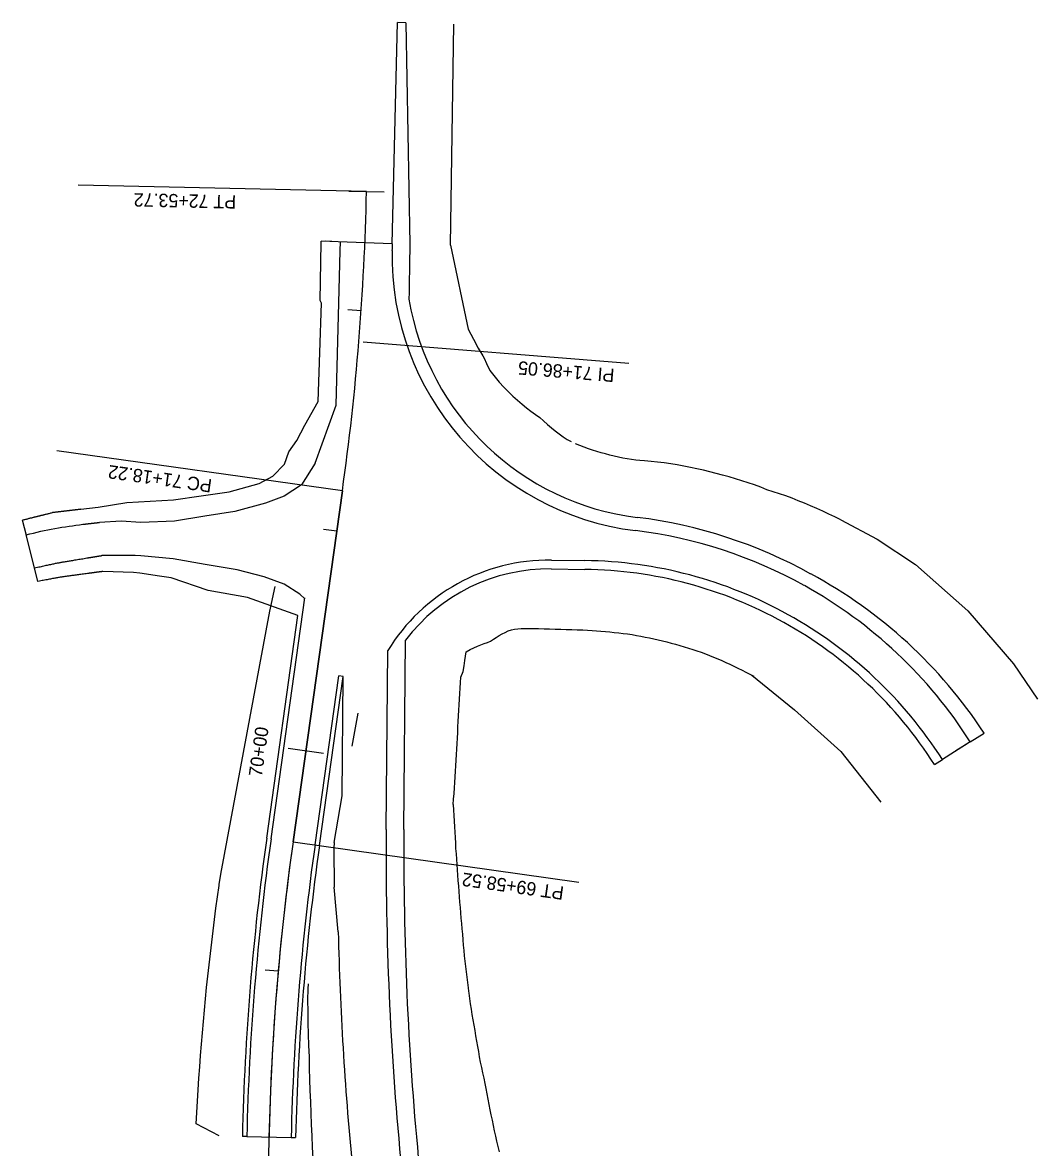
# Model space of a CAD drawing. Extents: x 1304554 to 1314558, y 2088110 to 2090513.
# Drawn here: x 1313853 to 1314311, y 2089937 to 2090444 of the extents above; entities that cross this region are included whole.
import ezdxf

# ---------------------------------------------------------------- set-up
doc = ezdxf.new("R2010")
doc.units = 0
for name, color, linetype in [('MOT_Striping_Stage 2B', 7, 'Continuous'), ('R_Horz Alg', 7, 'Continuous'), ('R_Horz Alg Annot', 7, 'Continuous'), ('R_Horz Alg Stationing', 7, 'Continuous'), ('R_Horz Alg Stationing_Side Road', 7, 'Continuous'), ('R_Proposed Const Limits', 7, 'Continuous'), ('R_Proposed Road', 7, 'Continuous'), ('R_Shoulder', 7, 'Continuous'), ('S_EDGE_PAVEMENT', 7, 'Continuous'), ('S_Striping', 7, 'Continuous')]:
    doc.layers.add(name, color=color, linetype=linetype)

msp = doc.modelspace()

# ---------------------------------------------------------------- linework, layer by layer
at = {"layer": 'MOT_Striping_Stage 2B'}
msp.add_lwpolyline([(1313980.63, 2090184.34), (1313978.35, 2090186.41), (1313971.27, 2090190.88), (1313962.27, 2090194.23), (1313950.11, 2090197.37), (1313935.68, 2090199.83), (1313921.26, 2090202.29), (1313906.77, 2090203.63), (1313904.2, 2090203.8), (1313889.17, 2090203.82)], dxfattribs=at)
for points in [[(1313858.82, 2090198.24), (1313866.61, 2090200.04), (1313874.52, 2090201.43), (1313882.45, 2090202.73)], [(1313882.45, 2090202.73), (1313884.69, 2090203.1), (1313886.93, 2090203.46), (1313889.17, 2090203.82)]]:
    msp.add_open_spline(points, degree=2, dxfattribs=at)
at = {"layer": 'R_Horz Alg'}
for p, q in [((1313997.56, 2090232.93), (1313975.33, 2090074.78)), ((1313975.33, 2090074.78), (1313997.56, 2090232.93))]:
    msp.add_line(p, q, dxfattribs=at)
for centre, start, end in [((1312862.79, 2090392.41), 352, 358.77499), ((1312862.79, 2090392.41), 352, 358.77499), ((1315110.09, 2089915.3), 172, 187), ((1315110.09, 2089915.3), 172, 178.67589)]:
    msp.add_arc(centre, 1145.92, start, end, dxfattribs=at)
at = {"layer": 'R_Horz Alg Annot'}
for points in [[(1314008.45, 2090367.91), (1313878.48, 2090370.69)], [(1314007, 2090300.1), (1314126.61, 2090290.45)], [(1313997.56, 2090232.93), (1313868.82, 2090251.02)], [(1313975.33, 2090074.78), (1314104.07, 2090056.69)]]:
    msp.add_lwpolyline(points, dxfattribs=at)
at = {"layer": 'R_Horz Alg Stationing'}
for points in [[(1314000.45, 2090368.08), (1314016.45, 2090367.74)], [(1314000.45, 2090368.08), (1314016.45, 2090367.74)], [(1314000.05, 2090314.66), (1314006.04, 2090314.25)], [(1313989.08, 2090215.72), (1313995.02, 2090214.89)], [(1313973.18, 2090116.97), (1313989.03, 2090114.75)], [(1313962.69, 2090017.18), (1313968.67, 2090016.65)]]:
    msp.add_lwpolyline(points, dxfattribs=at)
at = {"layer": 'R_Horz Alg Stationing_Side Road'}
msp.add_lwpolyline([(1314279.15, 2090118.99), (1314274.09, 2090115.77)], dxfattribs=at)
at = {"layer": 'R_Proposed Const Limits'}
for p, q in [((1314046.26, 2090343.75), (1314047.79, 2090443.25)), ((1313942.75, 2090060.17), (1313964.93, 2090178.72))]:
    msp.add_line(p, q, dxfattribs=at)
for points in [[(1314046.26, 2090343.75), (1314054.24, 2090305.79), (1314056.64, 2090301.31), (1314058.76, 2090297.34), (1314060.81, 2090293.79), (1314061.43, 2090292.78), (1314062.5, 2090290.38), (1314064.09, 2090287.15)], [(1314064.09, 2090287.15), (1314068.17, 2090281.94), (1314070.3, 2090279.69), (1314072.39, 2090277.59), (1314074.46, 2090275.63), (1314076.51, 2090273.78), (1314078.53, 2090272.04), (1314080.54, 2090270.39), (1314082.53, 2090268.84), (1314084.54, 2090267.42), (1314086.54, 2090266.08), (1314088.28, 2090264.49), (1314090, 2090262.93), (1314091.74, 2090261.44), (1314093.48, 2090260.01), (1314095.24, 2090258.64), (1314097.03, 2090257.37), (1314098.84, 2090256.16), (1314100.75, 2090255.18)], [(1314222.24, 2090219.87), (1314219.53, 2090221.2), (1314216.81, 2090222.5), (1314214.08, 2090223.76), (1314211.33, 2090224.99), (1314208.57, 2090226.19), (1314205.8, 2090227.36), (1314203.01, 2090228.49), (1314200.22, 2090229.61), (1314197.41, 2090230.67), (1314194.59, 2090231.69), (1314191.71, 2090232.57), (1314188.84, 2090233.45), (1314186.1, 2090234.65), (1314183.27, 2090235.64), (1314180.43, 2090236.58), (1314177.57, 2090237.49), (1314174.72, 2090238.4), (1314171.84, 2090239.24), (1314168.95, 2090240.03), (1314166.06, 2090240.79), (1314163.16, 2090241.54), (1314160.25, 2090242.26), (1314157.33, 2090242.9), (1314154.39, 2090243.5), (1314151.46, 2090244.08), (1314148.52, 2090244.67), (1314145.57, 2090245.15), (1314142.61, 2090245.58), (1314139.64, 2090245.96), (1314136.66, 2090246.22), (1314133.68, 2090246.48), (1314131.7, 2090246.62), (1314129.76, 2090246.81), (1314127.82, 2090247.05), (1314125.88, 2090247.35), (1314123.94, 2090247.7), (1314121.99, 2090248.1), (1314120.03, 2090248.56), (1314118.06, 2090249.07), (1314116.08, 2090249.6), (1314114.17, 2090250.11), (1314112.26, 2090250.67), (1314110.34, 2090251.28), (1314108.42, 2090251.94), (1314106.49, 2090252.64), (1314104.56, 2090253.4), (1314102.63, 2090254.21)], [(1314222.24, 2090219.87), (1314238.55, 2090211.26), (1314255.87, 2090199.73), (1314279.52, 2090178.98), (1314299.98, 2090154.96), (1314310.86, 2090139.11)], [(1313964.93, 2090178.72), (1313965.95, 2090183.63), (1313966.95, 2090188.54), (1313967.21, 2090189.8)], [(1313964.93, 2090178.72), (1313965.95, 2090183.63), (1313966.95, 2090188.54), (1313967.21, 2090189.8)], [(1314053.37, 2090160.46), (1314055.23, 2090161.43), (1314056.83, 2090162.21), (1314058.4, 2090162.92), (1314059.94, 2090163.57), (1314061.45, 2090164.15), (1314062.94, 2090164.67), (1314064.35, 2090165.28), (1314065.63, 2090166.14), (1314066.93, 2090166.96), (1314068.26, 2090167.74), (1314069.6, 2090168.47), (1314070.96, 2090169.17), (1314072.34, 2090169.83), (1314073.75, 2090170.4), (1314075.21, 2090170.68), (1314076.69, 2090170.85), (1314078.16, 2090170.92), (1314079.63, 2090170.95), (1314081.1, 2090170.93), (1314083.45, 2090170.91), (1314085.95, 2090170.88), (1314088.45, 2090170.84), (1314090.95, 2090170.76), (1314093.45, 2090170.69), (1314095.95, 2090170.62), (1314098.45, 2090170.55), (1314100.95, 2090170.48), (1314103.45, 2090170.39), (1314105.94, 2090170.28), (1314108.06, 2090170.18), (1314110.07, 2090170.05), (1314112.08, 2090169.91), (1314114.09, 2090169.75), (1314116.1, 2090169.59), (1314118.11, 2090169.41), (1314120.11, 2090169.2), (1314122.11, 2090168.98), (1314124.11, 2090168.74), (1314126.11, 2090168.48), (1314128.1, 2090168.19), (1314130.08, 2090167.85), (1314132.06, 2090167.48), (1314134.04, 2090167.09), (1314136.01, 2090166.69), (1314137.98, 2090166.27), (1314139.94, 2090165.82), (1314141.89, 2090165.36), (1314143.85, 2090164.88), (1314145.79, 2090164.38), (1314147.74, 2090163.85), (1314149.67, 2090163.31), (1314151.6, 2090162.74), (1314153.53, 2090162.15), (1314155.44, 2090161.54), (1314157.35, 2090160.91), (1314159.25, 2090160.25), (1314161.15, 2090159.58), (1314163.02, 2090158.84), (1314164.88, 2090158.07), (1314166.73, 2090157.27), (1314168.56, 2090156.45), (1314170.4, 2090155.64), (1314172.24, 2090154.81), (1314174.06, 2090153.96), (1314175.87, 2090153.09), (1314177.68, 2090152.21), (1314179.47, 2090151.3), (1314181.26, 2090150.37), (1314183.03, 2090149.42)], [(1314047.49, 2090091.6), (1314047.64, 2090094.1), (1314047.97, 2090096.6), (1314048.11, 2090099.1), (1314048.25, 2090101.6), (1314048.38, 2090104.09), (1314048.52, 2090106.59), (1314048.66, 2090109.09), (1314048.8, 2090111.59), (1314048.94, 2090114.09), (1314049.08, 2090116.59), (1314049.23, 2090119.09), (1314049.38, 2090121.59), (1314049.53, 2090124.09), (1314049.67, 2090126.58), (1314049.81, 2090129.08), (1314049.94, 2090131.58), (1314050.06, 2090134.08), (1314050.19, 2090136.58), (1314050.33, 2090139.08), (1314050.46, 2090141.58), (1314050.6, 2090144.08), (1314050.73, 2090146.58), (1314050.98, 2090149.07), (1314051.93, 2090151.57), (1314052.44, 2090154.06), (1314052.81, 2090156.56), (1314053.37, 2090160.46)], [(1314182.14, 2090149.89), (1314201.36, 2090134.34), (1314222.29, 2090115.49), (1314240.23, 2090092.69)], [(1314001.96, 2090117.98), (1314002.86, 2090122.9), (1314003.76, 2090127.82), (1314004.66, 2090132.75)], [(1314047.49, 2090091.6), (1314047.62, 2090089.1), (1314047.75, 2090086.6), (1314047.89, 2090084.1), (1314048.04, 2090081.6), (1314048.19, 2090079.13), (1314048.33, 2090076.7), (1314048.48, 2090074.27), (1314048.62, 2090071.85), (1314048.78, 2090069.42), (1314048.94, 2090067), (1314049.11, 2090064.58), (1314049.29, 2090062.15), (1314049.48, 2090059.73), (1314049.66, 2090057.31), (1314049.84, 2090054.89), (1314050.02, 2090052.47), (1314050.21, 2090050.05), (1314050.4, 2090047.63), (1314050.59, 2090045.21), (1314050.79, 2090042.79), (1314050.99, 2090040.38), (1314051.19, 2090037.96), (1314051.41, 2090035.54), (1314051.63, 2090033.13), (1314051.84, 2090030.71), (1314052.07, 2090028.3), (1314052.29, 2090025.88), (1314052.52, 2090023.47), (1314052.76, 2090021.06), (1314053, 2090018.65), (1314053.28, 2090016.24), (1314053.58, 2090013.83), (1314053.89, 2090011.42), (1314054.2, 2090009.02), (1314054.38, 2090007.58), (1314054.52, 2090006.61), (1314054.87, 2090004.21), (1314055.22, 2090001.81), (1314055.58, 2089999.41), (1314055.94, 2089997.01), (1314056.33, 2089994.61), (1314056.78, 2089992.22), (1314057.22, 2089989.82), (1314057.61, 2089987.43), (1314058.02, 2089985.04), (1314058.43, 2089982.64), (1314058.84, 2089980.25), (1314059.26, 2089977.87), (1314059.73, 2089975.48), (1314060.24, 2089973.1), (1314060.76, 2089970.72), (1314061.28, 2089968.34), (1314061.75, 2089965.96), (1314062.2, 2089963.58), (1314062.65, 2089961.2), (1314063.11, 2089958.82), (1314063.58, 2089956.45), (1314064.05, 2089954.07), (1314064.52, 2089951.7), (1314065, 2089949.33), (1314065.49, 2089946.95), (1314065.99, 2089944.58), (1314066.53, 2089942.22), (1314067.07, 2089939.86), (1314067.61, 2089937.5), (1314068.16, 2089935.1)], [(1313942.02, 2089942.3), (1313931.68, 2089947.69), (1313931.95, 2089952.82), (1313932.24, 2089957.96), (1313932.56, 2089963.09), (1313932.89, 2089968.23), (1313933.25, 2089973.36), (1313933.63, 2089978.48), (1313934.03, 2089983.61), (1313934.46, 2089988.73), (1313934.91, 2089993.85), (1313935.37, 2089998.97), (1313935.87, 2090004.09), (1313936.38, 2090009.2), (1313936.92, 2090014.31), (1313937.48, 2090019.42), (1313938.06, 2090024.53), (1313938.66, 2090029.63), (1313939.29, 2090034.73), (1313939.93, 2090039.82), (1313940.6, 2090044.91), (1313941.3, 2090050), (1313942.01, 2090055.09), (1313942.09, 2090055.65), (1313942.75, 2090060.17)], [(1313984.41, 2089932.13), (1313984.15, 2089937.22), (1313983.91, 2089942.32), (1313983.68, 2089947.41), (1313983.47, 2089952.5), (1313983.28, 2089957.59), (1313983.1, 2089962.68), (1313982.93, 2089967.77), (1313982.8, 2089972.87), (1313982.67, 2089977.96), (1313982.47, 2089983.04), (1313982.3, 2089988.13), (1313982.19, 2089993.22), (1313982.09, 2089998.31), (1313982, 2090003.4), (1313982.13, 2090008.49), (1313982.22, 2090010.82)]]:
    msp.add_lwpolyline(points, dxfattribs=at)
at = {"layer": 'R_Proposed Road'}
for p, q in [((1314019.98, 2090344.24), (1314022.48, 2090444.05)), ((1314019.98, 2090344.24), (1313995.73, 2090345.24)), ((1313858.82, 2090198.24), (1313855.07, 2090213.15)), ((1314091.76, 2090201.77), (1314106.88, 2090201.58)), ((1313965.43, 2090076.17), (1313980.7, 2090184.82)), ((1314017.33, 2090080.37), (1314018.03, 2090160.96)), ((1313985.23, 2090073.39), (1313995.95, 2090149.62)), ((1313997.93, 2090149.34), (1313995.95, 2090149.62)), ((1313997.46, 2090095.54), (1313997.93, 2090149.34)), ((1314280.55, 2090119.87), (1314267.99, 2090111.91)), ((1313993.79, 2090074.52), (1313997.46, 2090095.54)), ((1313995.67, 2090034.24), (1313993.84, 2090054.36)), ((1313954.49, 2089942.01), (1313974.48, 2089941.55))]:
    msp.add_line(p, q, dxfattribs=at)
for points in [[(1313994.77, 2090271.63), (1313995.38, 2090294.66), (1313995.99, 2090317.67), (1313996.55, 2090341.13), (1313996.65, 2090345.2)], [(1313985.31, 2090245.52), (1313994.77, 2090271.63)], [(1313985.31, 2090245.52), (1313979.1, 2090235.7), (1313971.37, 2090230.59), (1313962.91, 2090227.41), (1313949.15, 2090223.74), (1313935.56, 2090221.53), (1313921.97, 2090219.31), (1313906.66, 2090218.72), (1313897.86, 2090219.27), (1313888.06, 2090218.75)], [(1313980.63, 2090184.34), (1313978.35, 2090186.41), (1313971.27, 2090190.88), (1313962.27, 2090194.23), (1313950.11, 2090197.37), (1313935.68, 2090199.83), (1313921.26, 2090202.29), (1313906.77, 2090203.63), (1313904.2, 2090203.8), (1313889.17, 2090203.82)]]:
    msp.add_lwpolyline(points, dxfattribs=at)
for centre, radius, start, end in [((1314144.91, 2090339.12), 125, 178.9726, 263.0143), ((1321646.14, 2090204.59), 7627.44, 178.950936, 178.972554), ((1314104.34, 2090008.05), 208.54, 60.8986, 83.0143), ((1314090.65, 2090116.78), 85, 89.25, 148.6847), ((1314104.34, 2090008.05), 193.54, 60.8986, 89.25), ((1314104.62, 2090007.9), 208.54, 32.4747, 60.9853), ((1314104.86, 2090007.77), 193.54, 32.5535, 61.0751), ((1315437.67, 2090067.97), 1420.39, 179.5, 185.5), ((1315110.09, 2089915.3), 1155.92, 172, 178.67589), ((1315110.09, 2089915.3), 1135.92, 172, 178.67589), ((1315437.67, 2090067.97), 1443.89, 179.7402, 180.5402), ((1315437.67, 2090067.97), 1442.39, 181.3402, 185.5)]:
    msp.add_arc(centre, radius, start, end, dxfattribs=at)
for points in [[(1313880.58, 2090217.89), (1313883.07, 2090218.19), (1313885.56, 2090218.47), (1313888.06, 2090218.75)], [(1313882.45, 2090202.73), (1313884.69, 2090203.1), (1313886.93, 2090203.46), (1313889.17, 2090203.82)]]:
    msp.add_open_spline(points, degree=2, dxfattribs=at)
at = {"layer": 'R_Shoulder'}
for p, q in [((1314026.2, 2090443.93), (1314022.48, 2090444.05)), ((1314026.2, 2090443.93), (1314027.98, 2090344.09)), ((1313995.73, 2090345.24), (1313988.04, 2090345.56)), ((1313995.73, 2090345.24), (1313990.07, 2090345.48)), ((1313995.73, 2090345.24), (1313990.07, 2090345.48)), ((1313855.14, 2090212.86), (1313853.39, 2090219.81)), ((1313860.36, 2090192.15), (1313858.8, 2090198.32)), ((1314091.71, 2090197.77), (1314106.82, 2090197.58)), ((1313963.45, 2090076.45), (1313977.56, 2090176.87)), ((1314025.33, 2090080.3), (1314026.07, 2090165.68)), ((1313987.21, 2090073.11), (1313997.93, 2090149.34)), ((1314280.55, 2090119.87), (1314286.77, 2090123.82)), ((1314264.38, 2090109.61), (1314268, 2090111.91)), ((1313954.49, 2089942.01), (1313952.49, 2089942.06)), ((1313974.48, 2089941.55), (1313976.48, 2089941.5))]:
    msp.add_line(p, q, dxfattribs=at)
for points in [[(1313987.55, 2090318.7), (1313987.98, 2090344.82), (1313988.04, 2090345.56)], [(1313986.68, 2090273.24), (1313987.41, 2090295.4), (1313988.15, 2090317.56), (1313987.55, 2090318.7)], [(1313980.6, 2090262.64), (1313986.68, 2090273.24)], [(1313960.02, 2090236.31), (1313966.26, 2090239.58), (1313971.46, 2090245.07), (1313973.45, 2090250.62), (1313977.09, 2090255.73), (1313980.6, 2090262.64)], [(1313946.51, 2090232.61), (1313960.02, 2090236.31)], [(1313921.42, 2090228.88), (1313933.96, 2090230.74), (1313946.51, 2090232.61)], [(1313866.89, 2090223.18), (1313879.74, 2090224.69)], [(1313879.74, 2090224.69), (1313866.89, 2090223.18)], [(1313879.74, 2090224.69), (1313887.52, 2090225.61), (1313900.37, 2090227.68)], [(1313900.37, 2090227.68), (1313921.42, 2090228.88)], [(1313920.47, 2090193.74), (1313915.11, 2090194.55), (1313906.28, 2090195.89), (1313903.43, 2090196.16), (1313889.56, 2090196.62)], [(1313977.56, 2090176.87), (1313954.85, 2090184.99), (1313937.13, 2090188.03), (1313920.47, 2090193.74)]]:
    msp.add_lwpolyline(points, dxfattribs=at)
for centre, radius, start, end in [((1321646.14, 2090204.59), 7619.44, 178.950936, 179.137193), ((1314144.91, 2090339.12), 119, 189.5746, 263.0143), ((1314104.34, 2090008.05), 214.54, 60.8986, 82.9962), ((1314090.65, 2090116.78), 81, 89.25, 142.8665), ((1314104.34, 2090008.05), 189.54, 60.8986, 89.25), ((1314107.14, 2090006.52), 214.54, 33.145, 61.7515), ((1314104.34, 2090008.05), 189.54, 32.3985, 60.8986), ((1315437.67, 2090067.97), 1412.39, 179.5, 185.5), ((1315110.09, 2089915.3), 1157.92, 172, 178.67589), ((1315110.09, 2089915.3), 1133.92, 172, 178.67589)]:
    msp.add_arc(centre, radius, start, end, dxfattribs=at)
for points in [[(1313853.39, 2090219.81), (1313857.87, 2090220.98), (1313862.38, 2090222.08), (1313866.89, 2090223.18)], [(1313883.3, 2090195.8), (1313875.61, 2090194.78), (1313867.93, 2090193.67), (1313860.36, 2090192.15)], [(1313889.56, 2090196.62), (1313887.47, 2090196.35), (1313885.39, 2090196.08), (1313883.3, 2090195.8)]]:
    msp.add_open_spline(points, degree=2, dxfattribs=at)
at = {"layer": 'S_EDGE_PAVEMENT'}
for points, degree in [([(1313855.07, 2090213.15), (1313859.49, 2090214.31), (1313867.94, 2090216.21), (1313876.52, 2090217.39), (1313880.58, 2090217.89)], 3), ([(1313858.82, 2090198.24), (1313866.61, 2090200.04), (1313874.52, 2090201.43), (1313882.45, 2090202.73)], 2)]:
    msp.add_open_spline(points, degree=degree, dxfattribs=at)
at = {"layer": 'S_Striping'}
for points in [[(1313883.39, 2090218.22), (1313884.94, 2090218.4), (1313886.5, 2090218.58), (1313888.06, 2090218.75)], [(1313885.44, 2090203.22), (1313886.69, 2090203.42), (1313887.93, 2090203.62), (1313889.17, 2090203.82)]]:
    msp.add_open_spline(points, degree=2, dxfattribs=at)

# ---------------------------------------------------------------- texts
at = {"layer": 'R_Horz Alg Annot'}
for s, rotation, p in [('PT 72+53.72', 178.775, (1313949.77, 2090366.16)), ('PI 71+86.05', 175.3875, (1314120.39, 2090287.94)), ('PC 71+18.22', 172, (1313939.08, 2090238.12)), ('PC 71+18.22', 172, (1313939.08, 2090238.12)), ('PT 69+58.52', 172, (1314097.71, 2090054.55))]:
    msp.add_text(s, height=6, rotation=rotation, dxfattribs=at).set_placement(p)
at = {"layer": 'R_Horz Alg Stationing'}
msp.add_text('70+00', height=6, rotation=82, dxfattribs=at).set_placement((1313961.24, 2090103.86))

doc.saveas('drawing.dxf')
